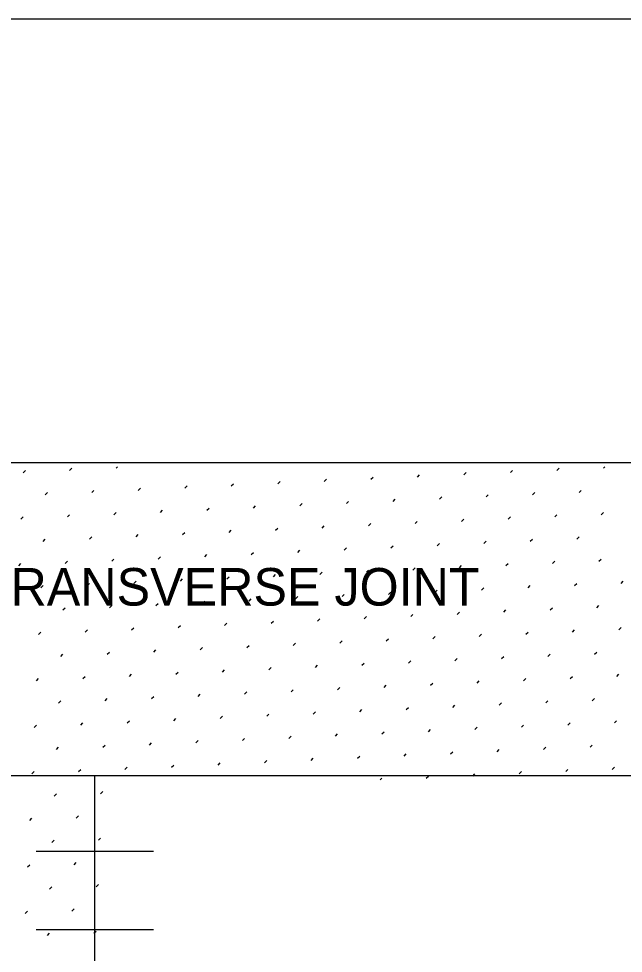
# Model space of a CAD drawing. Extents: x 49991.4 to 50021, y 49987.6 to 50011.4.
# Drawn here: x 50010.626 to 50011.591, y 49997.507 to 49998.999 of the extents above; entities that cross this region are included whole.
import ezdxf

# ---------------------------------------------------------------- set-up
doc = ezdxf.new("R2010")
doc.units = 0
for name, color, linetype in [('Level 1', 7, 'Continuous'), ('Level 10', 7, 'Continuous'), ('Level 2', 7, 'Continuous'), ('Level 4', 7, 'Continuous')]:
    doc.layers.add(name, color=color, linetype=linetype)

msp = doc.modelspace()

# ---------------------------------------------------------------- linework, layer by layer
at = {"layer": 'Level 1'}
for p, q in [((50015.1301, 49998.2903), (50001.3364, 49998.2903)), ((50010.7473, 49997.7903), (50008.8723, 49997.7903)), ((50010.7473, 49996.2915), (50010.7473, 49997.7903)), ((50011.6848, 49997.7903), (50010.7473, 49997.7903))]:
    msp.add_line(p, q, dxfattribs=at)
msp.add_lwpolyline([(49999.3835, 49998.9992), (50016.7501, 49998.9992), (50016.7501, 49987.7988), (49999.3835, 49987.7988)], close=True, dxfattribs=at)
at = {"layer": 'Level 10'}
for p, q in [((50010.7813, 49998.2815), (50010.7836, 49998.2838)), ((50011.4849, 49998.2781), (50011.4885, 49998.2816)), ((50011.5592, 49998.2816), (50011.5614, 49998.2838)), ((50010.6328, 49998.2744), (50010.6363, 49998.278)), ((50010.707, 49998.278), (50010.7106, 49998.2815)), ((50011.1879, 49998.2639), (50011.1914, 49998.2674)), ((50011.2622, 49998.2674), (50011.2657, 49998.271)), ((50011.3364, 49998.271), (50011.3399, 49998.2745)), ((50011.4107, 49998.2745), (50011.4142, 49998.278)), ((50010.8909, 49998.2497), (50010.8944, 49998.2532)), ((50010.9651, 49998.2533), (50010.9687, 49998.2568)), ((50011.0394, 49998.2568), (50011.0429, 49998.2603)), ((50011.1136, 49998.2603), (50011.1172, 49998.2639)), ((50010.6681, 49998.2391), (50010.6717, 49998.2426)), ((50010.7424, 49998.2426), (50010.7459, 49998.2462)), ((50010.8166, 49998.2462), (50010.8202, 49998.2497)), ((50011.3718, 49998.2356), (50011.3753, 49998.2391)), ((50011.446, 49998.2392), (50011.4496, 49998.2427)), ((50011.5203, 49998.2427), (50011.5238, 49998.2462)), ((50011.0748, 49998.2214), (50011.0783, 49998.225)), ((50011.149, 49998.225), (50011.1525, 49998.2285)), ((50011.2233, 49998.2285), (50011.2268, 49998.2321)), ((50011.2975, 49998.2321), (50011.301, 49998.2356)), ((50010.7035, 49998.2037), (50010.707, 49998.2073)), ((50010.7777, 49998.2073), (50010.7813, 49998.2108)), ((50010.852, 49998.2108), (50010.8555, 49998.2144)), ((50010.9262, 49998.2144), (50010.9298, 49998.2179)), ((50011.0005, 49998.2179), (50011.004, 49998.2214)), ((50011.4814, 49998.2038), (50011.4849, 49998.2073)), ((50011.5556, 49998.2073), (50011.5592, 49998.2109)), ((50010.6292, 49998.2002), (50010.6328, 49998.2037)), ((50011.1844, 49998.1896), (50011.1879, 49998.1932)), ((50011.2586, 49998.1932), (50011.2621, 49998.1967)), ((50011.3329, 49998.1967), (50011.3364, 49998.2003)), ((50011.4071, 49998.2003), (50011.4107, 49998.2038)), ((50010.8873, 49998.1755), (50010.8909, 49998.179)), ((50010.9616, 49998.179), (50010.9651, 49998.1825)), ((50011.0359, 49998.1825), (50011.0394, 49998.1861)), ((50011.1101, 49998.1861), (50011.1136, 49998.1896)), ((50010.6646, 49998.1648), (50010.6681, 49998.1684)), ((50010.7388, 49998.1684), (50010.7424, 49998.1719)), ((50010.8131, 49998.1719), (50010.8166, 49998.1755)), ((50011.3682, 49998.1614), (50011.3718, 49998.1649)), ((50011.4425, 49998.1649), (50011.446, 49998.1684)), ((50011.5167, 49998.1684), (50011.5203, 49998.172)), ((50011.0712, 49998.1472), (50011.0747, 49998.1507)), ((50011.1455, 49998.1507), (50011.149, 49998.1543)), ((50011.2197, 49998.1543), (50011.2233, 49998.1578)), ((50011.294, 49998.1578), (50011.2975, 49998.1614)), ((50010.6999, 49998.1295), (50010.7035, 49998.133)), ((50010.7742, 49998.133), (50010.7777, 49998.1366)), ((50010.8484, 49998.1366), (50010.852, 49998.1401)), ((50010.9227, 49998.1401), (50010.9262, 49998.1436)), ((50010.997, 49998.1436), (50011.0005, 49998.1472)), ((50011.4778, 49998.1295), (50011.4814, 49998.1331)), ((50011.5521, 49998.1331), (50011.5556, 49998.1366)), ((50010.6257, 49998.1259), (50010.6292, 49998.1295)), ((50011.1808, 49998.1154), (50011.1844, 49998.1189)), ((50011.2551, 49998.1189), (50011.2586, 49998.1225)), ((50011.3293, 49998.1225), (50011.3329, 49998.126)), ((50011.4036, 49998.126), (50011.4071, 49998.1295)), ((50010.8838, 49998.1012), (50010.8873, 49998.1047)), ((50010.9581, 49998.1047), (50010.9616, 49998.1083)), ((50011.0323, 49998.1083), (50011.0358, 49998.1118)), ((50011.1066, 49998.1118), (50011.1101, 49998.1154)), ((50010.661, 49998.0906), (50010.6646, 49998.0941)), ((50010.7353, 49998.0941), (50010.7388, 49998.0977)), ((50010.8096, 49998.0977), (50010.8131, 49998.1012)), ((50011.3647, 49998.0871), (50011.3682, 49998.0906)), ((50011.4389, 49998.0906), (50011.4425, 49998.0942)), ((50011.5132, 49998.0942), (50011.5167, 49998.0977)), ((50011.5874, 49998.0977), (50011.591, 49998.1013)), ((50010.9934, 49998.0694), (50010.9969, 49998.0729)), ((50011.0677, 49998.0729), (50011.0712, 49998.0765)), ((50011.1419, 49998.0765), (50011.1455, 49998.08)), ((50011.2162, 49998.08), (50011.2197, 49998.0836)), ((50011.2904, 49998.0836), (50011.294, 49998.0871)), ((50010.6964, 49998.0552), (50010.6999, 49998.0588)), ((50010.7707, 49998.0588), (50010.7742, 49998.0623)), ((50010.8449, 49998.0623), (50010.8484, 49998.0658)), ((50010.9192, 49998.0659), (50010.9227, 49998.0694)), ((50011.4743, 49998.0553), (50011.4778, 49998.0588)), ((50011.5485, 49998.0588), (50011.5521, 49998.0624)), ((50011.1773, 49998.0411), (50011.1808, 49998.0447)), ((50011.2515, 49998.0447), (50011.2551, 49998.0482)), ((50011.3258, 49998.0482), (50011.3293, 49998.0517)), ((50011.4, 49998.0518), (50011.4036, 49998.0553)), ((50010.8803, 49998.027), (50010.8838, 49998.0305)), ((50010.9545, 49998.0305), (50010.9581, 49998.034)), ((50011.0288, 49998.034), (50011.0323, 49998.0376)), ((50011.103, 49998.0376), (50011.1066, 49998.0411)), ((50010.6575, 49998.0163), (50010.661, 49998.0199)), ((50010.7318, 49998.0199), (50010.7353, 49998.0234)), ((50010.806, 49998.0234), (50010.8095, 49998.0269)), ((50011.3611, 49998.0129), (50011.3647, 49998.0164)), ((50011.4354, 49998.0164), (50011.4389, 49998.0199)), ((50011.5096, 49998.0199), (50011.5132, 49998.0235)), ((50011.5839, 49998.0235), (50011.5874, 49998.027)), ((50010.9899, 49997.9951), (50010.9934, 49997.9987)), ((50011.0641, 49997.9987), (50011.0677, 49998.0022)), ((50011.1384, 49998.0022), (50011.1419, 49998.0058)), ((50011.2126, 49998.0058), (50011.2162, 49998.0093)), ((50011.2869, 49998.0093), (50011.2904, 49998.0128)), ((50010.6929, 49997.981), (50010.6964, 49997.9845)), ((50010.7671, 49997.9845), (50010.7706, 49997.988)), ((50010.8414, 49997.9881), (50010.8449, 49997.9916)), ((50010.9156, 49997.9916), (50010.9192, 49997.9951)), ((50011.4707, 49997.981), (50011.4743, 49997.9846)), ((50011.545, 49997.9846), (50011.5485, 49997.9881)), ((50011.1737, 49997.9669), (50011.1773, 49997.9704)), ((50011.248, 49997.9704), (50011.2515, 49997.9739)), ((50011.3222, 49997.974), (50011.3258, 49997.9775)), ((50011.3965, 49997.9775), (50011.4, 49997.981)), ((50010.8767, 49997.9527), (50010.8803, 49997.9562)), ((50010.951, 49997.9562), (50010.9545, 49997.9598)), ((50011.0252, 49997.9598), (50011.0288, 49997.9633)), ((50011.0995, 49997.9633), (50011.103, 49997.9669)), ((50010.654, 49997.9421), (50010.6575, 49997.9456)), ((50010.7282, 49997.9456), (50010.7317, 49997.9492)), ((50010.8025, 49997.9492), (50010.806, 49997.9527)), ((50011.2833, 49997.9351), (50011.2869, 49997.9386)), ((50011.3576, 49997.9386), (50011.3611, 49997.9421)), ((50011.4318, 49997.9421), (50011.4354, 49997.9457)), ((50011.5061, 49997.9457), (50011.5096, 49997.9492)), ((50011.5804, 49997.9492), (50011.5839, 49997.9528)), ((50010.9863, 49997.9209), (50010.9899, 49997.9244)), ((50011.0606, 49997.9244), (50011.0641, 49997.928)), ((50011.1348, 49997.928), (50011.1384, 49997.9315)), ((50011.2091, 49997.9315), (50011.2126, 49997.9351)), ((50010.6893, 49997.9067), (50010.6929, 49997.9103)), ((50010.7636, 49997.9103), (50010.7671, 49997.9138)), ((50010.8378, 49997.9138), (50010.8414, 49997.9173)), ((50010.9121, 49997.9173), (50010.9156, 49997.9209)), ((50011.4672, 49997.9068), (50011.4707, 49997.9103)), ((50011.5415, 49997.9103), (50011.545, 49997.9139)), ((50011.1702, 49997.8926), (50011.1737, 49997.8962)), ((50011.2444, 49997.8962), (50011.248, 49997.8997)), ((50011.3187, 49997.8997), (50011.3222, 49997.9032)), ((50011.3929, 49997.9032), (50011.3965, 49997.9068)), ((50010.8732, 49997.8784), (50010.8767, 49997.882)), ((50010.9474, 49997.882), (50010.951, 49997.8855)), ((50011.0217, 49997.8855), (50011.0252, 49997.8891)), ((50011.0959, 49997.8891), (50011.0995, 49997.8926)), ((50010.6504, 49997.8678), (50010.654, 49997.8714)), ((50010.7247, 49997.8714), (50010.7282, 49997.8749)), ((50010.7989, 49997.8749), (50010.8025, 49997.8784)), ((50011.2798, 49997.8608), (50011.2833, 49997.8643)), ((50011.3541, 49997.8643), (50011.3576, 49997.8679)), ((50011.4283, 49997.8679), (50011.4318, 49997.8714)), ((50011.5026, 49997.8714), (50011.5061, 49997.875)), ((50011.5768, 49997.875), (50011.5803, 49997.8785)), ((50010.9828, 49997.8466), (50010.9863, 49997.8502)), ((50011.057, 49997.8502), (50011.0606, 49997.8537)), ((50011.1313, 49997.8537), (50011.1348, 49997.8573)), ((50011.2055, 49997.8573), (50011.2091, 49997.8608)), ((50010.6858, 49997.8325), (50010.6893, 49997.836)), ((50010.76, 49997.836), (50010.7636, 49997.8395)), ((50010.8343, 49997.8395), (50010.8378, 49997.8431)), ((50010.9085, 49997.8431), (50010.9121, 49997.8466)), ((50011.4637, 49997.8325), (50011.4672, 49997.8361)), ((50011.5379, 49997.8361), (50011.5414, 49997.8396)), ((50011.1666, 49997.8184), (50011.1702, 49997.8219)), ((50011.2409, 49997.8219), (50011.2444, 49997.8254)), ((50011.3152, 49997.8254), (50011.3187, 49997.829)), ((50011.3894, 49997.829), (50011.3929, 49997.8325)), ((50010.7954, 49997.8007), (50010.7989, 49997.8042)), ((50010.8696, 49997.8042), (50010.8732, 49997.8077)), ((50010.9439, 49997.8077), (50010.9474, 49997.8113)), ((50011.0181, 49997.8113), (50011.0217, 49997.8148)), ((50011.0924, 49997.8148), (50011.0959, 49997.8184)), ((50011.5733, 49997.8007), (50011.5768, 49997.8043)), ((50010.6469, 49997.7936), (50010.6504, 49997.7971)), ((50010.7211, 49997.7971), (50010.7247, 49997.8006)), ((50011.2763, 49997.7866), (50011.2798, 49997.7901)), ((50011.3505, 49997.7901), (50011.354, 49997.7936)), ((50011.4248, 49997.7936), (50011.4283, 49997.7972)), ((50011.499, 49997.7972), (50011.5026, 49997.8007)), ((50011.2028, 49997.7838), (50011.2055, 49997.7865)), ((50010.6822, 49997.7582), (50010.6858, 49997.7617)), ((50010.7565, 49997.7618), (50010.76, 49997.7653)), ((50010.6433, 49997.7193), (50010.6469, 49997.7228)), ((50010.7176, 49997.7229), (50010.7211, 49997.7264)), ((50010.6787, 49997.684), (50010.6822, 49997.6875)), ((50010.7529, 49997.6875), (50010.7565, 49997.691)), ((50010.6398, 49997.6451), (50010.6433, 49997.6486)), ((50010.714, 49997.6486), (50010.7176, 49997.6521)), ((50010.6751, 49997.6097), (50010.6787, 49997.6132)), ((50010.7494, 49997.6132), (50010.7529, 49997.6168)), ((50010.6362, 49997.5708), (50010.6398, 49997.5743)), ((50010.7105, 49997.5743), (50010.714, 49997.5779)), ((50010.6716, 49997.5355), (50010.6751, 49997.539)), ((50010.7459, 49997.539), (50010.7494, 49997.5425))]:
    msp.add_line(p, q, dxfattribs=at)
at = {"layer": 'Level 4'}
for p, q in [((50010.841, 49997.6695), (50010.6535, 49997.6695)), ((50010.841, 49997.5445), (50010.6535, 49997.5445))]:
    msp.add_line(p, q, dxfattribs=at)

# ---------------------------------------------------------------- texts
at = {"layer": 'Level 2'}
msp.add_text('EXISTING TRANSVERSE JOINT', height=0.06, dxfattribs=at).set_placement((50010.1668, 49998.0622))

doc.saveas('drawing.dxf')
